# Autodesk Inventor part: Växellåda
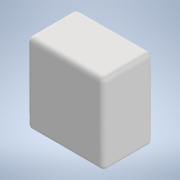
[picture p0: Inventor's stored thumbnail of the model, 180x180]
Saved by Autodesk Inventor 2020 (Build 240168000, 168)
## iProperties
Created: 2019-07
Part Number: Växellåda
Material: Generic
Document SubType Name: Modeling
Designer: cl
Density: 1 g/cm^3
Appearance: Default
Author: cl
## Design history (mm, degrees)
sketch "Sketch1"
  geometry: L1 (91.962, 166.577)-(-94.036, 165.737) reference; L2 (-94.036, 165.737)-(-93.783, 109.738) reference; L3 (-93.783, 109.738)-(-70.083, -45.157) reference; L4 (-70.083, -45.157)-(-69.293, -220.155) reference; L5 (-69.293, -220.155)-(70.705, -219.523) reference; L6 (70.705, -219.523)-(69.915, -44.525) reference; L7 (69.915, -44.525)-(92.215, 110.577) reference; L8 (92.215, 110.577)-(91.962, 166.577) reference; L9 (70.693, -216.76)-(-99.309, -216.76); L10 (-99.309, -216.76)-(-100.106, -40.292); L11 (-100.106, -40.292)-(69.893, -39.525); L12 (69.893, -39.525)-(70.693, -216.76); 7 further points
  constraints: 8 end point, 1 collinear, 1 horizontal, 1 parallel, 3 other
  dimensions: "d0" = 30 distance between parallel lines of L4 L10; "d1" = 180 distance between parallel lines of L5 L11
extrude "Extrusion1" new body sketch "Sketch1" distance "d2" = 110; taper "d3" = 0 deg
fillet "Fillet1" dims "d4" = 10
body "Solid1"
node "Reference1"
